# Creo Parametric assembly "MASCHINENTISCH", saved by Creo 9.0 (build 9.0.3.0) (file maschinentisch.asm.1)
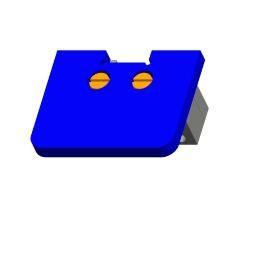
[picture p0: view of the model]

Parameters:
  ERSTELLER = "ARINDA"
  BENENNUNG = "XXX"
  TEILETYP = "K"

Other parameters: MASSE

Created from: ARINDA.ASM

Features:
  1. coordinate system "ACS0"
  2. datum plane "ADTM1", "A_RECHTS_Y-Z"
  3. datum plane "ADTM2", "A_OBEN_X-Z"
  4. datum plane "ADTM3", "A_VORNE_X-Y"
  5. datum axis "AA_X"
  6. datum axis "AA_2"
  7. datum axis "AA_Z"
  8. datum point "APNT0"
  9. component "MASCHINENTISCH"
  10. component "KONSOLE", "UNTERBAU_MASCHINENTISCH.PRT"
  11. pattern "Muster 1"
  12. component "ISO1207", "EI1207M4X5V4.PRT"
  13. component "ISO1207", "EI1207M4X5V4.PRT"
  14. component "FÜHRUNG_MASCHINENTISCH"
  15. component "FÜHRUNG_MASCHINENTISCH"
  16. component "ISO1207", "EI1207M4X5V4.PRT"
  17. component "ISO1207", "EI1207M4X5V4.PRT"
  18. pattern "Muster 2"
  19. component "ISO2338", "ISO2338A4X10.PRT"
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
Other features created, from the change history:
  datum axis "AA_1"
  datum plane "ADTM1"
  pattern "Muster 1"
  component "EI1207M4X5V4.PRT"
  pattern "Muster 2"
  component "ISO2338A4X10.PRT"
  component "ISO2338", "ISO2338A4X10.PRT" (3 times)
  pattern "Muster 3"

Other named items: AA_Y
